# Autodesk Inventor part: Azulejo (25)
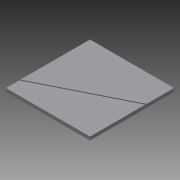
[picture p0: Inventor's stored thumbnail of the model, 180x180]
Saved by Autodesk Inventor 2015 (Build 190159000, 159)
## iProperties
Created: 2015-04
Part Number: Azulejo (25)
Material: Genérico
Document SubType Name: Modeling
Designer: Felipe
Density: 1 g/cm^3
Appearance: Padrão
Author: Felipe
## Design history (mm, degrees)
sketch "Sketch1"
  geometry: L1 (-1510, -7490)-(-1510, -6010); L2 (992.445, 7510)-(992.445, 8990); L3 (1012.445, 7510)-(1012.445, 8990); L4 (-3010, -1490)-(-3010, -10); L5 (-1510, 7490)-(-2990, 7490); L6 (-2990, 10)-(-1510, 10); L7 (-1510, -10)-(-2990, -10); L8 (-1510, -1490)-(-1510, -10); L9 (-10, 9010)-(-10, 10490); L10 (-10, 7510)-(-10, 8990); L11 (-10, 7490)-(-1490, 7490); L12 (-1490, 6010)-(-10, 6010); L13 (-10, 5990)-(-1490, 5990); L14 (-1490, -10)-(-1490, -1490); L15 (-1490, -1490)-(-10, -1490); L16 (-10, -1510)-(-1490, -1510); L17 (-10, -2990)-(-10, -1510); L18 (-10, -5990)-(-10, -4510); L19 (-1490, -7490)-(-10, -7490); L20 (10, 8990)-(10, 7510); L21 (1490, 7510)-(1490, 8990); L22 (10, 6010)-(1490, 6010); L23 (1490, 6010)-(1490, 7490); L24 (1490, 5990)-(10, 5990); L25 (4490, -6010)-(3010, -6010); L26 (10, -1510)-(10, -2990); L27 (10, -3010)-(10, -4490); L28 (10, -4510)-(10, -5990); L29 (10, -5990)-(1490, -5990); L30 (1490, -6010)-(10, -6010); L31 (10, -7490)-(1490, -7490); L32 (2990, 9010)-(2990, 10490); L33 (1510, 8990)-(1510, 7510); L34 (1510, 7510)-(2990, 7510); L35 (2990, 7490)-(1510, 7490); L36 (1510, 7490)-(1510, 6010); L37 (1510, -5990)-(2990, -5990); L38 (2990, -6010)-(1510, -6010); L39 (1510, -7490)-(2990, -7490); L40 (3010, 10490)-(3010, 9010); L41 (3010, 9010)-(4490, 9010); L42 (4490, 8990)-(3010, 8990); L43 (4490, 7490)-(3010, 7490); L44 (4490, 1510)-(4490, 2990); L45 (4490, 10)-(4490, 1490); L46 (4490, -1490)-(4490, -10); L47 (4490, -2990)-(4490, -1510); L48 (3010, -5990)-(4490, -5990); L49 (3010, -7490)-(4490, -7490); L50 (4510, 9010)-(5990, 9010); L51 (5990, 8990)-(4510, 8990); L52 (4510, 7510)-(5990, 7510); L53 (5990, 7490)-(4510, 7490); L54 (4510, 3010)-(5990, 3010); L55 (5990, 2990)-(4510, 2990); L56 (4510, 2990)-(4510, 1510); L57 (4510, 1510)-(5990, 1510); L58 (5990, 1510)-(5990, 1740.185); L59 (5990, 1760.2)-(5990, 2259.8); L60 (5990, 2279.815)-(5990, 2990); L61 (5990, 1490)-(4510, 1490); L62 (4510, 1490)-(4510, 10); L63 (4510, 10)-(5990, 10); L64 (5990, 10)-(5990, 1490)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; A1 r 250 centre (6000, 2010) between (5990, 2259.8) and (5990, 1760.2); A2 r 250 centre (6000, 2010) between (6010, 1760.2) and (6010, 2259.8); A3 r 270 centre (6000, 2010) between (5990, 2279.815) and (5990, 1740.185); A4 r 270 centre (6000, 2010) between (6010, 1740.185) and (6010, 2279.815); A5 r 3010.017 centre (0, 0) between (-1490, -2615.358) and (-346.554, -2990); A6 r 2990.017 centre (0, 0) between (-1490, -2592.316) and (-10, -2990); A7 r 3010.017 centre (0, 0) between (-2603.863, -1510) and (-1510, -2603.863); A8 r 2990.017 centre (0, 0) between (-2580.717, -1510) and (-1510, -2580.717); A9 r 3010.017 centre (0, 0) between (-2990, -346.554) and (-2615.358, -1490); A10 r 2990.017 centre (0, 0) between (-2990, -10) and (-2592.316, -1490); A11 r 2131.367 centre (7500, -1500) between (7490, 631.344) and (6010, 24.017); A12 r 2131.367 centre (7500, -1500) between (5975.983, -10) and (5368.656, -1490); A13 r 2131.367 centre (7500, -1500) between (5368.656, -1510) and (5975.983, -2990); A14 r 2131.367 centre (7500, -1500) between (6010, -3024.017) and (7190, -3608.703); A15 r 1831.367 centre (7500, -1500) between (7490.321, 331.342) and (6463.753, 10); A16 r 1831.367 centre (7500, -1500) between (6435.196, -10) and (6010, -435.196); A17 r 1831.367 centre (7500, -1500) between (5990, -463.753) and (5668.66, -1490); A18 r 1831.367 centre (7500, -1500) between (5668.66, -1510) and (5990, -2536.247); A19 r 1831.367 centre (7500, -1500) between (6010, -2564.804) and (6435.196, -2990); A20 r 1831.367 centre (7500, -1500) between (6463.753, -3010) and (7490, -3331.34); A21 r 2111.367 centre (7500, -1500) between (7490.047, 611.344) and (6024.272, 10); A22 r 2111.367 centre (7500, -1500) between (5990, -24.272) and (5388.656, -1490); A23 r 2111.367 centre (7500, -1500) between (5388.656, -1510) and (5990, -2975.728); A24 r 2111.367 centre (7500, -1500) between (6024.272, -3010) and (7210, -3591.357); A25 r 1811.367 centre (7500, -1500) between (7490.374, 311.342) and (6499.524, 10); A26 r 1811.367 centre (7500, -1500) between (6469.975, -10) and (6010, -469.975); A27 r 1811.367 centre (7500, -1500) between (5990, -499.524) and (5688.66, -1490); A28 r 1811.367 centre (7500, -1500) between (5688.66, -1510) and (5990, -2500.476); A29 r 1811.367 centre (7500, -1500) between (6010, -2530.025) and (6469.975, -2990); A30 r 1811.367 centre (7500, -1500) between (6499.524, -3010) and (7490, -3311.34); A31 r 449.871 centre (7499.449, -4060.672) between (7510, -4510.419) and (7521.546, -4510); 7 further points
  constraints: 1042 end point, 64 point on circle, 31 centre point, 13 point on line, 1 horizontal, 1 other
extrude "Extrusion1" new body sketch "Sketch1" distance "d0" = 60; taper "d1" = 0 deg
extrude "Extrusion2" new body sketch "Sketch1" distance "d2" = 60; taper "d3" = 0 deg
body "Solid1"
body "Solid2"
